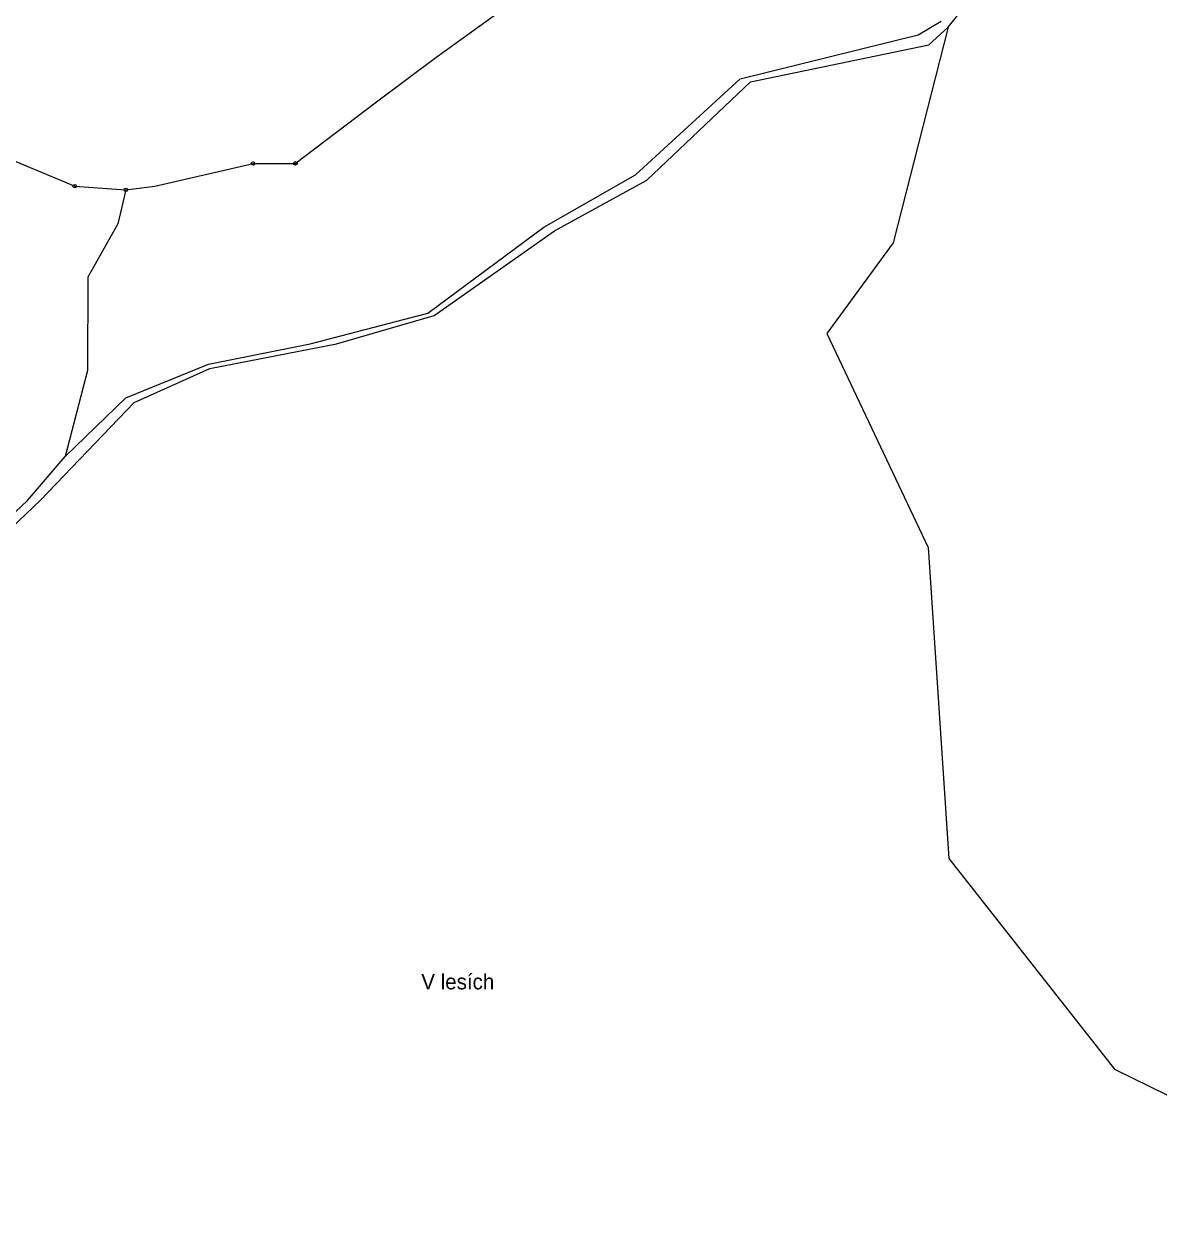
# Model space of a CAD drawing. Extents: x -601877 to -599786, y -1122905 to -1121218.
# Drawn here: x -601476.9 to -601151.3, y -1122096.2 to -1121749.5 of the extents above; entities that cross this region are included whole.
import ezdxf
from ezdxf.enums import TextEntityAlignment as Align

# ---------------------------------------------------------------- set-up
doc = ezdxf.new("R2010")
doc.units = 0
doc.header["$LTSCALE"] = 0.68
for name, color, linetype, lineweight in [('1', 7, 'Continuous', 25), ('7', 7, 'Continuous', 13), ('8', 7, 'Continuous', 25)]:
    doc.layers.add(name, color=color, linetype=linetype, lineweight=lineweight)

msp = doc.modelspace()

# ---------------------------------------------------------------- linework, layer by layer
at = {"layer": '1'}
for p, q in [((-601211.78, -1121750.4), (-601189.37, -1121722.16)), ((-601358.77, -1121759.06), (-601332.16, -1121739.88)), ((-601220.34, -1121752.57), (-601213.82, -1121748.69)), ((-601211.78, -1121750.4), (-601227.52, -1121812.26)), ((-601217.3, -1121755.47), (-601211.78, -1121750.4)), ((-601271.48, -1121765.22), (-601220.34, -1121752.57)), ((-601268.52, -1121766.07), (-601217.3, -1121755.47)), ((-601375.8, -1121771.81), (-601358.77, -1121759.06)), ((-601301.52, -1121792.78), (-601271.48, -1121765.22)), ((-601298.22, -1121794.25), (-601268.52, -1121766.07)), ((-601399.12, -1121789.47), (-601375.8, -1121771.81)), ((-601489.29, -1121784.81), (-601462.41, -1121796.01)), ((-601439.41, -1121796.05), (-601411.24, -1121789.5)), ((-601411.24, -1121789.5), (-601399.12, -1121789.47)), ((-601327.75, -1121807.77), (-601301.52, -1121792.78)), ((-601462.41, -1121796.01), (-601447.74, -1121797.05)), ((-601447.74, -1121797.05), (-601450.06, -1121806.82)), ((-601447.74, -1121797.05), (-601439.41, -1121796.05)), ((-601324.73, -1121808.78), (-601298.22, -1121794.25)), ((-601450.06, -1121806.82), (-601458.64, -1121822.12)), ((-601361.07, -1121832.41), (-601327.75, -1121807.77)), ((-601359.26, -1121833.1), (-601324.73, -1121808.78)), ((-601458.64, -1121822.12), (-601458.75, -1121848.87)), ((-601394.85, -1121841.24), (-601361.07, -1121832.41)), ((-601387.31, -1121841.24), (-601359.26, -1121833.1)), ((-601424.04, -1121847.03), (-601394.85, -1121841.24)), ((-601423.61, -1121848.29), (-601387.31, -1121841.24)), ((-601458.75, -1121848.87), (-601465.13, -1121873.51)), ((-601447.75, -1121856.71), (-601424.04, -1121847.03)), ((-601445.38, -1121858.08), (-601423.61, -1121848.29)), ((-601472.22, -1121886.04), (-601445.38, -1121858.08)), ((-601465.13, -1121873.51), (-601447.75, -1121856.71)), ((-601475.94, -1121886.16), (-601465.13, -1121873.51)), ((-601498.48, -1121907.26), (-601475.94, -1121886.16)), ((-601495.65, -1121908.27), (-601472.22, -1121886.04)), ((-601217.5, -1121899.61), (-601211.57, -1121988.8)), ((-601211.57, -1121988.8), (-601164.03, -1122049.26)), ((-601164.03, -1122049.26), (-601068.69, -1122096.18))]:
    msp.add_line(p, q, dxfattribs=at)
msp.add_lwpolyline([(-601227.52, -1121812.26), (-601246.6, -1121838.28), (-601217.5, -1121899.61)], dxfattribs=at)
at = {"layer": '8'}
for centre, radius in [((-601411.24, -1121789.4999), 0.5), ((-601411.24, -1121789.4999), 0.0303), ((-601399.12, -1121789.4699), 0.5), ((-601399.12, -1121789.4699), 0.0303), ((-601462.41, -1121796.0099), 0.5), ((-601462.41, -1121796.0099), 0.0303), ((-601447.74, -1121797.0499), 0.5), ((-601447.74, -1121797.0499), 0.0303)]:
    msp.add_circle(centre, radius, dxfattribs=at)

# ---------------------------------------------------------------- texts
at = {"layer": '7'}
msp.add_text('V lesích', height=4.4, dxfattribs=at).set_placement((-601352.489, -1122026.36), align=Align.CENTER)

doc.saveas('drawing.dxf')
